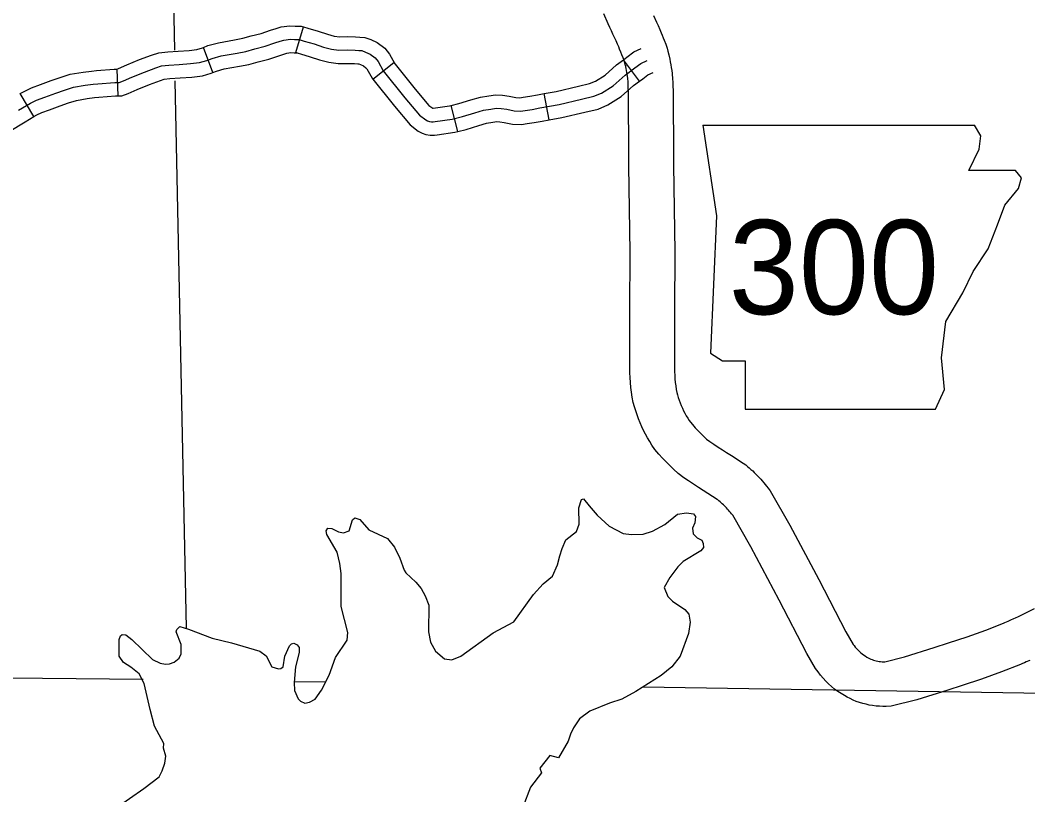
# Model space of a CAD drawing. Extents: x -19 to 366, y -4 to 359.
# Drawn here: x 138.218 to 139.286, y 201.956 to 202.778 of the extents above; entities that cross this region are included whole.
import ezdxf

# ---------------------------------------------------------------- set-up
doc = ezdxf.new("R2010")
doc.units = 0
for name, color, linetype in [('Level 10', 7, 'Continuous'), ('Level 21', 7, 'Continuous'), ('Level 32', 7, 'Continuous'), ('Level 5', 7, 'Continuous'), ('Level 60', 7, 'Continuous'), ('Level 9', 7, 'Continuous')]:
    doc.layers.add(name, color=color, linetype=linetype)

msp = doc.modelspace()

# ---------------------------------------------------------------- linework, layer by layer
at = {"layer": 'Level 10'}
for p, q in [((138.8594, 202.7297), (138.8595, 202.7291)), ((138.9597, 202.267), (138.9598, 202.2669))]:
    msp.add_line(p, q, dxfattribs=at)
for points in [[(138.8595, 202.7291), (138.8585, 202.7332), (138.858, 202.7351), (138.8578, 202.7359), (138.8571, 202.7376), (138.8557, 202.7407), (138.8545, 202.7437), (138.8532, 202.7469), (138.8523, 202.7493), (138.8511, 202.752), (138.8495, 202.7555), (138.8462, 202.7626), (138.8445, 202.7662), (138.8429, 202.7699), (138.8413, 202.7735), (138.8366, 202.7842)], [(138.8892, 202.7824), (138.8925, 202.7753), (138.8941, 202.7718), (138.8961, 202.7675), (138.8973, 202.7642), (138.8984, 202.7615), (138.8995, 202.7588), (138.9006, 202.7562), (138.9023, 202.7521), (138.9036, 202.7479), (138.9044, 202.7448), (138.9055, 202.7406)], [(138.9055, 202.7406), (138.9064, 202.7363), (138.907, 202.7334), (138.9076, 202.7303), (138.9081, 202.7272), (138.9086, 202.7242), (138.909, 202.7208), (138.9095, 202.7149), (138.9096, 202.7121), (138.9098, 202.7093), (138.91, 202.701), (138.91, 202.6979), (138.9099, 202.6928), (138.9104, 202.6407), (138.9105, 202.6236), (138.9117, 202.5318), (138.9115, 202.4694), (138.9116, 202.413), (138.9115, 202.4086), (138.9115, 202.4048), (138.9117, 202.401), (138.9119, 202.3972), (138.9123, 202.3934), (138.9128, 202.3897), (138.9134, 202.386), (138.914, 202.3827), (138.9147, 202.3802), (138.9155, 202.3774), (138.9164, 202.3746), (138.9175, 202.3716), (138.9186, 202.3689), (138.9198, 202.3661), (138.9211, 202.3634), (138.9225, 202.3607), (138.924, 202.358), (138.9255, 202.3555), (138.9271, 202.3529), (138.9283, 202.3512), (138.9305, 202.3487), (138.9335, 202.3453), (138.9366, 202.342), (138.9398, 202.3388), (138.943, 202.3357), (138.9455, 202.3334), (138.9489, 202.3309), (138.9533, 202.3279), (138.9577, 202.3249), (138.9623, 202.3219), (138.9668, 202.319), (138.9719, 202.316), (138.9844, 202.3079), (138.987, 202.3059), (138.9889, 202.3043), (138.9906, 202.3028)], [(138.9598, 202.2669), (138.9585, 202.268), (138.9573, 202.269), (138.9567, 202.2694), (138.9469, 202.2758), (138.942, 202.2787), (138.9368, 202.282), (138.9316, 202.2854), (138.9264, 202.2889), (138.9213, 202.2924), (138.9153, 202.2968), (138.9104, 202.3013), (138.9064, 202.3052), (138.9025, 202.3092), (138.8988, 202.3132), (138.895, 202.3173), (138.8907, 202.3223), (138.8876, 202.3269), (138.8852, 202.3306), (138.8829, 202.3345), (138.8807, 202.3384), (138.8787, 202.3424), (138.8768, 202.3464), (138.8749, 202.3505), (138.8733, 202.3547), (138.8718, 202.3589), (138.8703, 202.3632), (138.869, 202.3675), (138.8678, 202.3722), (138.8667, 202.3778), (138.8659, 202.383), (138.8653, 202.3882), (138.8647, 202.3933), (138.8644, 202.3985), (138.8642, 202.4037), (138.8641, 202.4089), (138.8642, 202.4135), (138.8641, 202.4694), (138.8644, 202.5316), (138.8632, 202.6231), (138.863, 202.6403), (138.8626, 202.6931), (138.8627, 202.6983), (138.8627, 202.7002), (138.8625, 202.7072), (138.8623, 202.7094), (138.8622, 202.7117), (138.8619, 202.716), (138.8617, 202.7177), (138.8613, 202.7201), (138.861, 202.7221), (138.8606, 202.7241), (138.8601, 202.7264), (138.8594, 202.7297)], [(138.9906, 202.3028), (138.9926, 202.3011), (138.9944, 202.2995), (138.9961, 202.2978), (138.9979, 202.2961), (138.9996, 202.2943), (139.0013, 202.2926), (139.0029, 202.2908), (139.0045, 202.289), (139.0062, 202.2871), (139.0078, 202.2852), (139.0092, 202.2833), (139.0107, 202.2814), (139.0128, 202.2785), (139.0339, 202.242), (139.0644, 202.1844), (139.0932, 202.1291), (139.1011, 202.1157), (139.102, 202.1143), (139.1032, 202.1128), (139.1045, 202.1112), (139.1059, 202.1097), (139.1073, 202.1083), (139.1088, 202.107), (139.1104, 202.1057), (139.112, 202.1045), (139.1137, 202.1034), (139.1156, 202.1022), (139.117, 202.1014), (139.1184, 202.1007), (139.1198, 202.1), (139.1212, 202.0995), (139.1226, 202.099), (139.124, 202.0985), (139.1255, 202.0981), (139.1271, 202.0978), (139.1285, 202.0976), (139.13, 202.0974), (139.1316, 202.0972), (139.1331, 202.0972), (139.1344, 202.0972), (139.1555, 202.1025), (139.1868, 202.1123), (139.202, 202.1172), (139.2219, 202.1236), (139.2416, 202.1306), (139.2603, 202.1381), (139.2618, 202.1388), (139.2636, 202.1395), (139.2653, 202.1403), (139.2688, 202.1419), (139.2705, 202.1426), (139.274, 202.1443), (139.2755, 202.145), (139.2932, 202.1538)], [(139.2884, 202.0987), (139.2846, 202.097), (139.2825, 202.0961), (139.2806, 202.0953), (139.2784, 202.0944), (139.2584, 202.0864), (139.2371, 202.0787), (139.2164, 202.0721), (139.2012, 202.0672), (139.1684, 202.0569), (139.1413, 202.0501), (139.1359, 202.0499), (139.1323, 202.0498), (139.1288, 202.05), (139.1252, 202.0503), (139.1216, 202.0507), (139.1181, 202.0513), (139.1146, 202.0521), (139.1111, 202.0529), (139.1077, 202.054), (139.1043, 202.0552), (139.101, 202.0566), (139.0977, 202.0581), (139.0946, 202.0597), (139.0916, 202.0614), (139.0882, 202.0635), (139.0847, 202.0658), (139.0813, 202.0683), (139.078, 202.071), (139.0749, 202.0738), (139.0719, 202.0768), (139.069, 202.0798), (139.0663, 202.083), (139.0637, 202.0864), (139.0611, 202.0902), (139.0517, 202.1061), (139.0224, 202.1625), (138.9925, 202.2191), (138.9732, 202.2525), (138.9729, 202.2529), (138.9719, 202.2542), (138.9709, 202.2555), (138.9699, 202.2567), (138.9689, 202.2578), (138.9678, 202.259), (138.9667, 202.2603), (138.9656, 202.2614), (138.9644, 202.2626), (138.9633, 202.2637), (138.9622, 202.2648), (138.961, 202.2659), (138.9597, 202.267)]]:
    msp.add_lwpolyline(points, dxfattribs=at)
at = {"layer": 'Level 21'}
for p, q in [((138.9415, 202.6663), (138.9559, 202.5701)), ((139.2363, 202.655), (139.2296, 202.6661)), ((139.2347, 202.6406), (139.2363, 202.655)), ((139.2235, 202.6182), (139.2347, 202.6406)), ((139.2731, 202.6182), (139.2235, 202.6182)), ((139.2795, 202.6102), (139.2731, 202.6182)), ((139.2763, 202.599), (139.2795, 202.6102)), ((139.2619, 202.5813), (139.2763, 202.599)), ((139.2539, 202.5605), (139.2619, 202.5813)), ((138.9559, 202.5701), (138.9495, 202.4243)), ((139.2443, 202.5349), (139.2539, 202.5605)), ((139.2283, 202.5109), (139.2443, 202.5349)), ((139.2171, 202.4884), (139.2283, 202.5109)), ((139.1994, 202.458), (139.2171, 202.4884)), ((139.1946, 202.4195), (139.1994, 202.458)), ((138.9495, 202.4243), (138.9623, 202.4163)), ((138.9623, 202.4163), (138.9864, 202.4163)), ((138.9864, 202.4163), (138.9864, 202.3651)), ((139.1978, 202.3859), (139.1946, 202.4195)), ((139.1882, 202.3651), (139.1978, 202.3859)), ((138.9864, 202.3651), (139.1882, 202.3651))]:
    msp.add_line(p, q, dxfattribs=at)
msp.add_lwpolyline([(138.9415, 202.6663), (139.2296, 202.6661)], dxfattribs=at)
at = {"layer": 'Level 32'}
for p, q in [((138.51, 202.7432), (138.518, 202.7704)), ((138.422, 202.7221), (138.4118, 202.7486)), ((138.8745, 202.7129), (138.8574, 202.7356)), ((138.3213, 202.6973), (138.3204, 202.7256)), ((138.5916, 202.7149), (138.6138, 202.7327)), ((138.2321, 202.6752), (138.2175, 202.6996)), ((138.7786, 202.6717), (138.7734, 202.6997)), ((138.6816, 202.6594), (138.6746, 202.687))]:
    msp.add_line(p, q, dxfattribs=at)
for points in [[(138.4118, 202.7486), (138.4167, 202.7505), (138.4277, 202.7535), (138.4449, 202.7566), (138.4536, 202.7583), (138.4626, 202.7608), (138.4732, 202.7635), (138.483, 202.7668), (138.4889, 202.7687), (138.4943, 202.7703), (138.5035, 202.7716), (138.5091, 202.7713), (138.5156, 202.7711), (138.518, 202.7704)], [(138.518, 202.7704), (138.5227, 202.769), (138.5335, 202.7659), (138.5433, 202.7626), (138.5505, 202.7607), (138.5564, 202.76), (138.5651, 202.7601), (138.5732, 202.7598), (138.5776, 202.7596), (138.5829, 202.7591), (138.5893, 202.7569), (138.596, 202.7537), (138.6042, 202.7479), (138.6091, 202.7416), (138.6145, 202.7318), (138.6138, 202.7327)], [(138.2158, 202.682), (138.2284, 202.6895), (138.235, 202.6927), (138.2438, 202.6959), (138.2552, 202.7001), (138.2644, 202.7033), (138.274, 202.7063), (138.2864, 202.7085), (138.2948, 202.7095), (138.2998, 202.71), (138.3178, 202.7114), (138.3226, 202.7115), (138.327, 202.7131), (138.336, 202.717), (138.3495, 202.7225), (138.3614, 202.7271), (138.3674, 202.729), (138.3753, 202.7298), (138.3862, 202.7305), (138.3983, 202.7314), (138.4079, 202.7326), (138.4156, 202.7349), (138.4212, 202.737), (138.4308, 202.7396), (138.4475, 202.7426), (138.4569, 202.7444), (138.4663, 202.7471), (138.4772, 202.7499), (138.4875, 202.7533), (138.4931, 202.7552), (138.4972, 202.7563), (138.5041, 202.7573), (138.5085, 202.7571), (138.5135, 202.7569), (138.5187, 202.7554), (138.5292, 202.7523), (138.5392, 202.749), (138.5477, 202.7468), (138.5556, 202.7457), (138.565, 202.7459), (138.5727, 202.7456), (138.5767, 202.7455), (138.5798, 202.7452), (138.5839, 202.7437), (138.5888, 202.7414), (138.5942, 202.7375), (138.5972, 202.7337), (138.6026, 202.7239), (138.6256, 202.6953), (138.6411, 202.6768), (138.6476, 202.6719), (138.6495, 202.6708), (138.6515, 202.6701), (138.6536, 202.6698), (138.6557, 202.6698), (138.6578, 202.6701), (138.6757, 202.6726), (138.6867, 202.6754), (138.6997, 202.6794), (138.7089, 202.6821), (138.7166, 202.6833), (138.7223, 202.6842), (138.7278, 202.6839), (138.7336, 202.683), (138.7414, 202.6813), (138.7483, 202.681), (138.7532, 202.6818), (138.7604, 202.6829), (138.7688, 202.6844), (138.789, 202.6881), (138.8129, 202.6936), (138.826, 202.6969), (138.8342, 202.7002), (138.8464, 202.7079), (138.8591, 202.7191), (138.8694, 202.7268), (138.8759, 202.7316), (138.8825, 202.7348)], [(138.32, 202.7256), (138.3218, 202.7263), (138.3305, 202.7301), (138.3442, 202.7357), (138.3567, 202.7405), (138.3645, 202.743), (138.3741, 202.7439), (138.3852, 202.7446), (138.3969, 202.7455), (138.405, 202.7465), (138.411, 202.7483), (138.4118, 202.7486)], [(138.8574, 202.7356), (138.861, 202.7382), (138.8685, 202.7438), (138.8763, 202.7476)], [(138.422, 202.7221), (138.4256, 202.7235), (138.434, 202.7258), (138.4501, 202.7286), (138.4602, 202.7306), (138.47, 202.7334), (138.4812, 202.7362), (138.492, 202.7398), (138.4973, 202.7416), (138.5002, 202.7424), (138.5047, 202.7431), (138.508, 202.7429), (138.5113, 202.7428), (138.51, 202.7432)], [(138.51, 202.7432), (138.5147, 202.7418), (138.525, 202.7388), (138.5351, 202.7354), (138.545, 202.7328), (138.5548, 202.7315), (138.5648, 202.7317), (138.5721, 202.7314), (138.5758, 202.7313), (138.5767, 202.7312), (138.5785, 202.7306), (138.5816, 202.7291), (138.5843, 202.7271), (138.5853, 202.7258), (138.5908, 202.7159), (138.5917, 202.7149)], [(138.7734, 202.6997), (138.7861, 202.702), (138.8096, 202.7074), (138.8215, 202.7104), (138.8277, 202.7129), (138.8379, 202.7193), (138.8501, 202.7301), (138.8574, 202.7356)], [(138.2175, 202.6996), (138.2217, 202.702), (138.2295, 202.7059), (138.239, 202.7092), (138.2504, 202.7135), (138.26, 202.7168), (138.2706, 202.7201), (138.2843, 202.7225), (138.2932, 202.7236), (138.2985, 202.7242), (138.3171, 202.7255), (138.3204, 202.7256)], [(138.6138, 202.7327), (138.6366, 202.7043), (138.651, 202.6872), (138.6551, 202.6841), (138.6557, 202.6842), (138.6729, 202.6866), (138.6746, 202.687)], [(138.3213, 202.6973), (138.3253, 202.6974), (138.3322, 202.6999), (138.3415, 202.7039), (138.3547, 202.7093), (138.3662, 202.7137), (138.3702, 202.715), (138.3764, 202.7156), (138.3872, 202.7163), (138.3997, 202.7172), (138.4109, 202.7186), (138.4202, 202.7214), (138.422, 202.7221)], [(138.5916, 202.7149), (138.6147, 202.6862), (138.6313, 202.6665), (138.6398, 202.6599), (138.6437, 202.6578), (138.6479, 202.6563), (138.6523, 202.6556), (138.6568, 202.6556), (138.6599, 202.6561), (138.6784, 202.6586), (138.6816, 202.6594)], [(138.7786, 202.6717), (138.7919, 202.6742), (138.8163, 202.6798), (138.8304, 202.6833), (138.8407, 202.6876), (138.855, 202.6965), (138.8681, 202.7081), (138.8745, 202.7129)], [(138.8745, 202.7129), (138.8779, 202.7154), (138.8833, 202.7194), (138.8888, 202.7221)], [(138.2321, 202.6752), (138.2352, 202.677), (138.2405, 202.6796), (138.2487, 202.6825), (138.2599, 202.6867), (138.2688, 202.6898), (138.2774, 202.6925), (138.2885, 202.6944), (138.2965, 202.6954), (138.3011, 202.6959), (138.3185, 202.6972), (138.3213, 202.6973)], [(138.6746, 202.687), (138.6828, 202.6891), (138.6956, 202.6931), (138.7057, 202.6959), (138.7144, 202.6974), (138.7216, 202.6984), (138.7292, 202.6981), (138.7362, 202.697), (138.7433, 202.6955), (138.7475, 202.6953), (138.7509, 202.6958), (138.7581, 202.6969), (138.7663, 202.6983), (138.7734, 202.6997)], [(138.1309, 202.6434), (138.138, 202.6427), (138.1466, 202.643), (138.1549, 202.644), (138.1606, 202.6449), (138.1677, 202.6448), (138.1739, 202.645), (138.1826, 202.6473), (138.2057, 202.6595), (138.223, 202.6698), (138.2321, 202.6752)], [(138.6816, 202.6594), (138.6905, 202.6617), (138.7038, 202.6658), (138.712, 202.6682), (138.7188, 202.6693), (138.723, 202.6699), (138.7264, 202.6698), (138.731, 202.6691), (138.7396, 202.6672), (138.7492, 202.6668), (138.7554, 202.6678), (138.7627, 202.6689), (138.7713, 202.6704), (138.7786, 202.6717)]]:
    msp.add_lwpolyline(points, dxfattribs=at)
at = {"layer": 'Level 5'}
for points in [[(138.3744, 203.0767), (138.3811, 202.7458)], [(138.3817, 202.7132), (138.3935, 202.1328)], [(138.348, 202.0783), (137.3863, 202.0879)], [(138.5414, 202.0755), (138.5081, 202.0761)], [(139.3944, 202.0621), (138.8779, 202.0702)]]:
    msp.add_lwpolyline(points, dxfattribs=at)
at = {"layer": 'Level 60'}
for points in [[(146.7783, 1.697), (146.5788, 10.3131), (146.3785, 18.9294), (146.1776, 27.5458), (145.9759, 36.1624), (145.7736, 44.7791), (145.5705, 53.396), (145.3668, 62.013), (145.1624, 70.6301), (144.9572, 79.2474), (144.7514, 87.8648), (144.5449, 96.4823), (144.3377, 105.1), (144.1299, 113.7179), (143.9213, 122.3359), (143.712, 130.954), (143.5021, 139.5723), (143.2915, 148.1907), (143.0802, 156.8092), (142.8682, 165.4279), (142.6555, 174.0468), (142.4422, 182.6658), (142.2282, 191.2849), (142.0135, 199.9042), (141.7981, 208.5236), (141.582, 217.1432), (141.3653, 225.7629), (141.1479, 234.3828), (140.9298, 243.0028), (140.711, 251.623), (140.4916, 260.2433), (140.2715, 268.8638), (140.0508, 277.4844), (139.8293, 286.1051), (139.6072, 294.726), (139.3845, 303.3471), (139.161, 311.9683), (138.937, 320.5896), (138.7122, 329.2111), (138.4868, 337.8328), (138.2607, 346.4546)], [(139.4406, 1.5315), (139.2511, 10.1473), (139.0608, 18.7633), (138.8699, 27.3793), (138.6784, 35.9956), (138.4861, 44.6119), (138.2932, 53.2285), (138.0997, 61.8451), (137.9055, 70.4619), (137.7106, 79.0789), (137.5151, 87.6959), (137.319, 96.3132), (137.1221, 104.9306), (136.9247, 113.5481), (136.7265, 122.1658), (136.5278, 130.7836), (136.3283, 139.4016), (136.1282, 148.0197), (135.9275, 156.6379), (135.7261, 165.2564), (135.5241, 173.8749), (135.3214, 182.4936), (135.1181, 191.1125), (134.9141, 199.7315), (134.7095, 208.3506), (134.5043, 216.9699), (134.2984, 225.5894), (134.0919, 234.209), (133.8847, 242.8288), (133.6769, 251.4487), (133.4685, 260.0687), (133.2594, 268.6889), (133.0497, 277.3093), (132.8393, 285.9298), (132.6283, 294.5504), (132.4167, 303.1713), (132.2044, 311.7922), (131.9916, 320.4133), (131.778, 329.0346), (131.5639, 337.656), (131.3491, 346.2776)], [(0, 198.1326), (7.1014, 198.137), (14.2028, 198.1503), (21.3042, 198.1724), (28.4055, 198.2034), (35.5068, 198.2433), (42.6081, 198.292), (49.7092, 198.3496), (56.8103, 198.4161), (63.9113, 198.4913), (71.0123, 198.5755), (78.1131, 198.6685), (85.2137, 198.7704), (92.3143, 198.8811), (99.4147, 199.0007), (106.5149, 199.1291), (113.615, 199.2664), (120.7149, 199.4126), (127.8146, 199.5676), (134.9141, 199.7315), (142.0135, 199.9042), (149.1125, 200.0858), (156.2114, 200.2762), (163.31, 200.4755), (170.4084, 200.6837), (177.5065, 200.9007), (184.6043, 201.1265), (191.7018, 201.3612), (198.799, 201.6048), (205.896, 201.8572), (212.9926, 202.1185), (220.0888, 202.3886), (227.1848, 202.6676), (234.2803, 202.9554), (241.3755, 203.2521), (248.4704, 203.5576), (255.5648, 203.872), (262.6589, 204.1952), (269.7525, 204.5273), (276.8457, 204.8682), (283.9385, 205.218), (291.0309, 205.5766), (298.1228, 205.9441), (305.2142, 206.3204), (312.3051, 206.7056), (319.3956, 207.0996), (326.4856, 207.5024), (333.5751, 207.9141), (340.664, 208.3347)]]:
    msp.add_spline(points, degree=3, dxfattribs=at)
at = {"layer": 'Level 9'}
for points in [[(138.7899, 202.2097), (138.7922, 202.2173), (138.7964, 202.2264), (138.8077, 202.2352), (138.8103, 202.2431), (138.8099, 202.2606), (138.813, 202.2693), (138.8148, 202.2701), (138.8209, 202.2625), (138.8296, 202.2526), (138.8421, 202.2409), (138.8572, 202.2333), (138.8659, 202.2321), (138.8784, 202.2325), (138.8882, 202.2356), (138.9014, 202.2428), (138.9146, 202.2538), (138.9241, 202.2553), (138.9317, 202.2542), (138.9339, 202.2511), (138.9332, 202.2447), (138.9305, 202.239), (138.9313, 202.2329), (138.9355, 202.2288), (138.9404, 202.2261), (138.9419, 202.2227), (138.9423, 202.2185), (138.9393, 202.2147), (138.9207, 202.2037), (138.9151, 202.198), (138.9064, 202.1866), (138.9007, 202.176), (138.9045, 202.1665), (138.9094, 202.1616), (138.9223, 202.1525), (138.9268, 202.1476), (138.928, 202.1392), (138.9265, 202.1271), (138.9174, 202.1032), (138.9087, 202.0918), (138.8974, 202.0827), (138.8706, 202.0656), (138.8555, 202.0576), (138.8426, 202.0535), (138.8218, 202.0447), (138.8109, 202.0368), (138.8045, 202.0273), (138.8011, 202.0205), (138.7988, 202.0129), (138.7886, 201.9954), (138.7792, 201.9977), (138.7686, 201.9844), (138.7705, 201.9795), (138.7588, 201.9643), (138.7505, 201.9431)], [(138.3837, 202.1315), (138.3867, 202.1345), (138.3961, 202.1318), (138.4211, 202.1224), (138.4415, 202.1174), (138.4718, 202.1084), (138.4786, 202.1034), (138.4846, 202.092), (138.4914, 202.0898), (138.4941, 202.0902), (138.4963, 202.092), (138.4982, 202.1031), (138.5031, 202.1141), (138.5054, 202.1163), (138.5077, 202.1171), (138.5114, 202.1152), (138.5133, 202.1122), (138.5133, 202.1072), (138.5096, 202.0917), (138.5081, 202.0754), (138.5085, 202.0666), (138.5122, 202.0579), (138.5149, 202.0553), (138.5194, 202.0534), (138.5243, 202.0545), (138.5304, 202.0575), (138.5372, 202.067), (138.5451, 202.083), (138.5519, 202.1016), (138.5644, 202.1201), (138.5651, 202.1281), (138.5579, 202.1558), (138.5579, 202.1907), (138.5567, 202.2013), (138.5537, 202.2135), (138.5427, 202.232), (138.5419, 202.2362), (138.5438, 202.2389), (138.548, 202.2385), (138.5552, 202.2351), (138.5605, 202.2339), (138.5665, 202.2362), (138.5699, 202.2476), (138.5726, 202.2499), (138.5778, 202.248), (138.5873, 202.237), (138.607, 202.2279), (138.6145, 202.2188), (138.6202, 202.207), (138.6248, 202.1945), (138.6267, 202.1915), (138.6373, 202.1816), (138.6429, 202.1748), (138.6471, 202.1672), (138.6509, 202.1573), (138.6505, 202.1289), (138.6528, 202.1179), (138.6581, 202.1084), (138.6676, 202.1005), (138.6755, 202.0993), (138.685, 202.1031), (138.7193, 202.1278), (138.7412, 202.1395), (138.762, 202.1684), (138.7722, 202.1798), (138.782, 202.1881), (138.7873, 202.1999), (138.7899, 202.2097)], [(138.3184, 201.9418), (138.3487, 201.963), (138.3649, 201.9752), (138.3683, 201.9816), (138.3709, 201.9896), (138.3721, 201.9972), (138.3694, 202.0055), (138.3698, 202.0105), (138.3599, 202.029), (138.3554, 202.0465), (138.3489, 202.0742), (138.3436, 202.0844), (138.3349, 202.0916), (138.327, 202.0965), (138.3224, 202.103), (138.3224, 202.1208), (138.3239, 202.1246), (138.3258, 202.1261), (138.3296, 202.1258), (138.336, 202.1208), (138.358, 202.0996), (138.3659, 202.0958), (138.3716, 202.0947), (138.3758, 202.095), (138.3807, 202.0969), (138.386, 202.1011), (138.3882, 202.1057), (138.3882, 202.1155), (138.3829, 202.1288), (138.3837, 202.1315)]]:
    msp.add_lwpolyline(points, dxfattribs=at)

# ---------------------------------------------------------------- texts
at = {"layer": 'Level 21'}
msp.add_text('300', height=0.1, dxfattribs=at).set_placement((138.969, 202.4657))

doc.saveas('drawing.dxf')
